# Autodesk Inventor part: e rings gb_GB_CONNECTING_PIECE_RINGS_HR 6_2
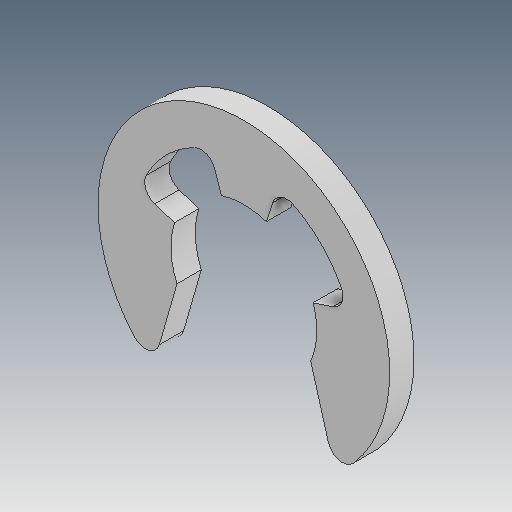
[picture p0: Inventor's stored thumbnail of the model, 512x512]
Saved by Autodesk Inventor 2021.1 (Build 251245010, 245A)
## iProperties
Created: 2019-04
Part Number: e rings gb_GB_CONNECTING_PIECE_RINGS_HR 6_2
Material: Ogólny
Document SubType Name: Modeling
Designer: user
Density: 1 g/cm^3
Appearance: Domyślna
Author: user
Revision Number: ÈÎºÎ
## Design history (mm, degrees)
feature "ÊäÈë1"
node "Bryła1"
